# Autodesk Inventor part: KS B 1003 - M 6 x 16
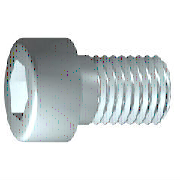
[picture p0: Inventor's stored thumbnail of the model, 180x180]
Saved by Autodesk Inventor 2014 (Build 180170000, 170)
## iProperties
Created: 2009-02
Part Number: KS B 1003 - M 6 x 16
Material: Steel, Mild
Description: 6각머리 태핑 나사
Document SubType Name: Modeling
Standard: KS B 1003
Designer: KYOUNG IL JANG
Standards Organization: KS
Language: ko-KR
Size Designation: M 6 x 16
Categories: <MemberInstance><Categories><Category DisplayName="조임쇠" InternalName="e4da775c-781d-43d5-af7c-5136215cf5a6" Mnemonic="FSTN"><Category DisplayName="볼트" InternalN
Density: 1 g/cm^3
Appearance: Metal-Steel
Company: 한국ATC센터
IsCustomPart: 0
Author: KYOUNG IL JANG
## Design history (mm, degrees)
sketch "스케치1"
  geometry: L1 (-1.333, 0)-(16, 0); L2 (16, 0)-(16, 3); L3 (16, 3)-(2.5, 3); L4 (2.5, 3)-(1.886, 3); L5 (1.886, 3)-(0, 3); L6 (0, 3)-(0, 5); L7 (0, 5)-(-6, 5); L8 (-6, 5)-(-6, 2.887); L9 (-6, 2.887)-(-3, 2.887); L10 (-3, 2.887)-(-1.333, 0); L11 (-10.4, 0)-(20.4, 0) reference; L12 (0, -1)-(0, 6) reference; L13 (2.5, 3)-(0, 3)
  constraints: 22 end point, 6 parallel, 2 collinear, 2 perpendicular, 1 horizontal, 1 point on line
  dimensions: "d1" = 13.5 distance from line of L3.end L2 (= GEL); "d2" = 0.61355 distance of L4.end L3.end (computed from GAL); "d3" = 6 distance between parallel lines of L8 L6 (= KOH); "d4" = 3 distance of L8.end L9.end (= INTI); "d5" = 60 deg angle of L10 L1; "d6" = 6 diameter of L3 L1 (= GD); "d7" = 6 diameter of L5 L1 (= BDM); "d8" = 5.7735 diameter of L9 L1 (= 1.1547 x SW); "d9" = 10 diameter of L7 L1 (= KOD); "d26" = 16 distance between parallel lines of L12 L2 (= NLG)
revolve "본체" sketch "스케치1" stored, may be unused: angle "d10" = 90 deg
sketch "스케치2"
  geometry: L1 (0, -7)-(0, 7) reference; L2 (-7, 0)-(7, 0) reference; L3 (2.887, 0)-(1.443, -2.5); L4 (1.443, -2.5)-(-1.443, -2.5); L5 (-1.443, -2.5)-(-2.887, 0); L6 (-2.887, 0)-(-1.443, 2.5); L7 (-1.443, 2.5)-(1.443, 2.5); L8 (1.443, 2.5)-(2.887, 0); 2 further points
  constraints: 12 end point, 1 coincident, 1 horizontal alignment, 1 point on line, 12 other
extrude "슬롯" join sketch "스케치2" stored distance "d11" = 10; taper "d12" = 0 deg
workplane "Work Plane1"
fillet "Fillet2" dims "d30" = 0.1 (= R)
body "Solid1"
fillet "모깎기1" dims "d17" = 0.6 (= RR)
feature "스레드" dims "d13" = 13.5 (= GEL), "d14" = 0
chamfer "모따기1" distance "d15" = 0.61345 (= -0.5 x SPD + 0.5 x GD); stored, may be unused: second distance "d16" = 0.61345 (= GUL), angle "d27" = 45 deg
other parameters: "GD" = 6 (= NND) [user parameter; used in 2 equation terms], "NLG" = 16 [user parameter; used in 1 equation term], "GEL" = 13.5 [user parameter; used in 2 equation terms], "KOD" = 10 [user parameter; used in 1 equation term], "KOH" = 6 [user parameter; used in 1 equation term], "INTI" = 3 [user parameter; used in 1 equation term], "GAL" = 0.61345 (= 0.61345 x PTC) [user parameter; used in 1 equation term], "GUL" = 0.61345 (= 0.61345 x PTC) [user parameter; used in 1 equation term], "BDM" = 6 (= NND) [user parameter; used in 1 equation term], "SW" = 5 [user parameter; used in 2 equation terms], "RR" = 0.6 [user parameter; used in 1 equation term], "SPD" = 4.7731 (= NND - 1.2269 x PTC) [user parameter; used in 1 equation term], "d19" = 0, "d28" = 0, "d29" = 0, "R" = 0.1 [user parameter; used in 1 equation term], "PHH" = 0.25 [user parameter], "GD1" = 4.7731 (= THREADDIA - 1.2269 x PTC) [user parameter], "THREADDIA" = 6 [user parameter; used in 1 equation term], "FAWI" = 45 deg [user parameter], "PTC" = 1 [user parameter; used in 5 equation terms], "NND" = 6 [user parameter; used in 3 equation terms], "TOA" = 30 deg [user parameter], "E0" = 5.775 (= 1.155 x SW) [user parameter]
